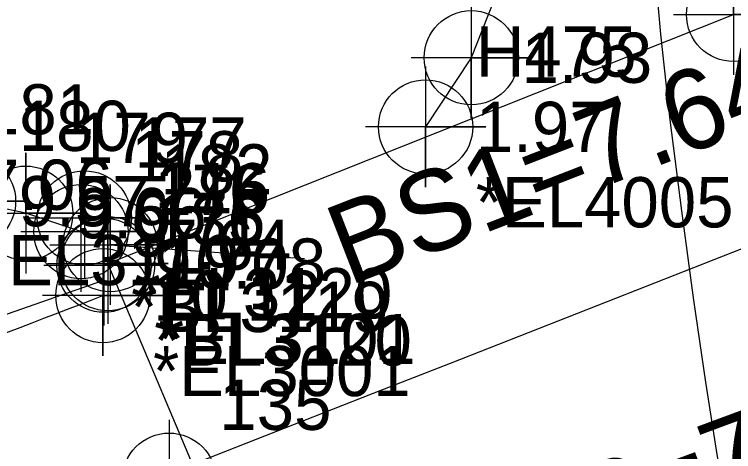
# Model space of a CAD drawing. Extents: x 2597630 to 2605918, y 617194 to 635093.
# Drawn here: x 2604047.61 to 2604083.41, y 618689.44 to 618711.2 of the extents above; entities that cross this region are included whole.
import ezdxf

# ---------------------------------------------------------------- set-up
doc = ezdxf.new("R2010")
doc.units = 0
for name, color, linetype in [('COGO Default Chain', 7, 'Continuous'), ('COGO Default Curve', 7, 'Continuous'), ('Exist DTM Breakline', 7, 'Continuous'), ('Exist DTM Breakline Cogo Comment', 7, 'Continuous'), ('Exist DTM Breakline Cogo Elevation', 7, 'Continuous'), ('Exist DTM Breakline Cogo Number', 7, 'Continuous'), ('Exist DTM Breakline Cogo Point CELL', 7, 'Continuous'), ('Exist DTM Crownline Cogo Number', 7, 'Continuous'), ('Exist DTM Crownline Cogo Point CELL', 7, 'Continuous'), ('Exist Guardrail', 7, 'Continuous'), ('Exist Horizontal Alignment', 7, 'Continuous'), ('Exist Hydro Stream or Body of Water', 7, 'Continuous'), ('Exist Right of Way Line', 7, 'Continuous'), ('Exist Roads EOP', 7, 'Continuous'), ('Exist Roads EOP Cogo Comment', 7, 'Continuous'), ('Exist Roads EOP Cogo Elevation', 7, 'Continuous'), ('Exist Roads EOP Cogo Number', 7, 'Continuous'), ('Exist Roads EOP Cogo Point CELL', 7, 'Continuous'), ('Exist Structure Major Bridge Seat Cogo Elevation', 7, 'Continuous'), ('Exist Structure Major Bridge Seat Cogo Number', 7, 'Continuous'), ('Exist Structure Major Bridge Seat Cogo Point CELL', 7, 'Continuous'), ('Exist Structure Major Bridge Seat Leader', 7, 'Continuous'), ('Exist Structure Major Bridge Seat Top Elevation', 7, 'Continuous'), ('Exist Structure Major Bridge WW', 7, 'Continuous'), ('Exist Structure Major Bridge WW Cogo Comment', 7, 'Continuous'), ('Exist Structure Major Bridge WW Cogo Elevation', 7, 'Continuous'), ('Exist Structure Major Bridge WW Cogo Number', 7, 'Continuous'), ('Exist Structure Major Bridge WW Cogo Point CELL', 7, 'Continuous'), ('Exist Structure Major Deck Tunnel Box Culvert', 7, 'Continuous'), ('Exist Structure Major Deck Tunnel Box Culvert Cogo Comment', 7, 'Continuous'), ('Exist Structure Major Deck Tunnel Box Culvert Cogo Elevation', 7, 'Continuous'), ('Exist Structure Major Deck Tunnel Box Culvert Cogo Number', 7, 'Continuous'), ('Exist Structure Major Deck Tunnel Box Culvert Cogo Point CELL', 7, 'Continuous'), ('Exist Structure Minor Head and End Wall Cogo Comment', 7, 'Continuous'), ('Exist Structure Minor Head and End Wall Cogo Elevation', 7, 'Continuous'), ('Exist Structure Minor Head and End Wall Cogo Number', 7, 'Continuous'), ('Exist Structure Minor Head and End Wall Cogo Point CELL', 7, 'Continuous')]:
    doc.layers.add(name, color=color, linetype=linetype)

# ---------------------------------------------------------------- blocks, each defined once
blk = doc.blocks.new('EXIST DTM BREAKLINE COGO POINT')
at = {"layer": 'Exist DTM Breakline Cogo Point CELL'}
blk.add_lwpolyline([(0, 0.06), (0, -0.06), (0, 0), (0.06, 0), (-0.06, 0)], dxfattribs=at)
blk.add_circle((0, 0), 0.04688, dxfattribs=at)
blk = doc.blocks.new('EXIST STRUCTURE MAJOR BRIDGE SEAT COGO POINT')
at = {"layer": 'Exist Structure Major Bridge Seat Cogo Point CELL'}
blk.add_lwpolyline([(-0.06, 0), (0.06, 0), (0, 0), (0, 0.06), (0, -0.06)], dxfattribs=at)
blk.add_circle((0, 0), 0.04688, dxfattribs=at)
blk = doc.blocks.new('EXIST DTM CROWNLINE COGO POINT')
at = {"layer": 'Exist DTM Crownline Cogo Point CELL'}
blk.add_lwpolyline([(0, 0.06), (0, -0.06), (0, 0), (0.06, 0), (-0.06, 0)], dxfattribs=at)
blk.add_circle((0, 0), 0.04688, dxfattribs=at)
blk = doc.blocks.new('EXIST ROADS EOP COGO POINT')
at = {"layer": 'Exist Roads EOP Cogo Point CELL'}
blk.add_lwpolyline([(0, 0.06), (0, -0.06), (0, 0), (0.06, 0), (-0.06, 0)], dxfattribs=at)
blk.add_circle((0, 0), 0.04688, dxfattribs=at)
blk = doc.blocks.new('EXIST STRUCTURE MINOR HEAD AND END WALL COGO POINT')
at = {"layer": 'Exist Structure Minor Head and End Wall Cogo Point CELL'}
blk.add_lwpolyline([(-0.06, 0), (0.06, 0), (0, 0), (0, 0.06), (0, -0.06)], dxfattribs=at)
blk.add_circle((0, 0), 0.04688, dxfattribs=at)
blk = doc.blocks.new('EXIST STRUCTURE MAJOR BRIDGE WW COGO POINT')
at = {"layer": 'Exist Structure Major Bridge WW Cogo Point CELL'}
blk.add_lwpolyline([(-0.06, 0), (0.06, 0), (0, 0), (0, 0.06), (0, -0.06)], dxfattribs=at)
blk.add_circle((0, 0), 0.04688, dxfattribs=at)
blk = doc.blocks.new('EXIST STRUCTURE MAJOR DECK TUNNEL BOX CULVERT COGO POINT')
at = {"layer": 'Exist Structure Major Deck Tunnel Box Culvert Cogo Point CELL'}
blk.add_lwpolyline([(-0.06, 0), (0.06, 0), (0, 0), (0, 0.06), (0, -0.06)], dxfattribs=at)
blk.add_circle((0, 0), 0.04688, dxfattribs=at)

msp = doc.modelspace()

# ---------------------------------------------------------------- linework, layer by layer
at = {"layer": 'COGO Default Chain'}
msp.add_arc((2597632.588, 635089.507), 17613.895, 290.3221155, 292.0583016, dxfattribs=at)
msp.add_arc((2597632.588, 635089.507), 17613.895, 290.3221155, 292.0583016, dxfattribs=at)
msp.add_arc((2597632.588, 635089.507), 17613.895, 290.3221155, 292.0583016, dxfattribs=at)
msp.add_arc((2597632.588, 635089.507), 17613.895, 290.3221155, 292.0583016, dxfattribs=at)
msp.add_arc((2597632.588, 635089.507), 17613.895, 290.3221155, 292.0583016, dxfattribs=at)
msp.add_arc((2597632.588, 635089.507), 17613.895, 290.3221155, 292.0583016, dxfattribs=at)
at = {"layer": 'COGO Default Curve'}
msp.add_arc((2597632.588, 635089.507), 17613.895, 290.3221155, 292.0583016, dxfattribs=at)
msp.add_arc((2597632.588, 635089.507), 17613.895, 290.3221155, 292.0583016, dxfattribs=at)
at = {"layer": 'Exist DTM Breakline'}
msp.add_lwpolyline([(2604073.23, 618725.574), (2604072.597, 618714.752), (2604070.352, 618709.039), (2604068.079, 618705.596)], dxfattribs=at)
at = {"layer": 'Exist Guardrail'}
msp.add_lwpolyline([(2604027.029, 618690.238), (2604028.032, 618689.57), (2604052.016, 618697.945)], dxfattribs=at)
at = {"layer": 'Exist Horizontal Alignment'}
msp.add_arc((2597632.588, 635089.507), 17613.895, 290.3221155, 292.0583016, dxfattribs=at)
at = {"layer": 'Exist Hydro Stream or Body of Water'}
msp.add_lwpolyline([(2604079.436, 618713.93), (2604079.767, 618710.215), (2604080.243, 618705.943), (2604080.811, 618701.424), (2604081.419, 618696.971), (2604082.012, 618692.895), (2604082.539, 618689.506), (2604082.793, 618687.973), (2604083.043, 618686.561), (2604083.41, 618684.573), (2604083.483, 618684.153)], dxfattribs=at)
at = {"layer": 'Exist Right of Way Line'}
msp.add_arc((2597632.588, 635089.507), 17584.22, 290.3221155, 291.5057379, dxfattribs=at)
at = {"layer": 'Exist Roads EOP'}
msp.add_spline([(2603230.17, 618389.98), (2603282.929, 618409.597), (2603332.773, 618427.868), (2603388.167, 618448.413), (2603437.203, 618466.721), (2603490.778, 618486.527), (2603539.039, 618504.558), (2603597.451, 618526.156), (2603651.053, 618545.972), (2603705.208, 618566.084), (2603762.02, 618587.183), (2603820.334, 618609.162), (2603876.341, 618629.99), (2603934.909, 618652.28), (2603996.409, 618675.568), (2604033.216, 618689.957), (2604052.01, 618697.199)], degree=3, dxfattribs=at)
at = {"layer": 'Exist Structure Major Bridge Seat Leader'}
msp.add_lwpolyline([(2604052.378, 618699.736), (2604062.046, 618699.043), (2604062.046, 618699.043)], dxfattribs=at)
at = {"layer": 'Exist Structure Major Bridge WW'}
msp.add_lwpolyline([(2604050.92, 618700.387), (2604048.172, 618701.305), (2604045.325, 618701.901), (2604043.496, 618702.72)], dxfattribs=at)
at = {"layer": 'Exist Structure Major Deck Tunnel Box Culvert'}
for p, q in [((2604052.256, 618698.794), (2604083.412, 618711.197)), ((2604052.256, 618698.794), (2604083.412, 618711.197)), ((2604061.588, 618676.727), (2604052.256, 618698.794)), ((2604061.588, 618676.727), (2604052.256, 618698.794))]:
    msp.add_line(p, q, dxfattribs=at)

# ---------------------------------------------------------------- block references
at = {"layer": 'Exist DTM Breakline Cogo Point CELL', "xscale": 50, "yscale": 50}
for p in [(2604070.352, 618709.039), (2604068.079, 618705.596)]:
    msp.add_blockref('EXIST DTM BREAKLINE COGO POINT', p, dxfattribs=at)
at = {"layer": 'Exist DTM Crownline Cogo Point CELL', "xscale": 50, "yscale": 50}
msp.add_blockref('EXIST DTM CROWNLINE COGO POINT', (2604055.311, 618688.017), dxfattribs=at)
msp.add_blockref('EXIST DTM CROWNLINE COGO POINT', (2604055.311, 618688.017), dxfattribs=at)
at = {"layer": 'Exist Roads EOP Cogo Point CELL', "xscale": 50, "yscale": 50}
msp.add_blockref('EXIST ROADS EOP COGO POINT', (2604052.01, 618697.199), dxfattribs=at)
msp.add_blockref('EXIST ROADS EOP COGO POINT', (2604052.01, 618697.199), dxfattribs=at)
at = {"layer": 'Exist Structure Major Bridge Seat Cogo Point CELL', "xscale": 50, "yscale": 50}
msp.add_blockref('EXIST STRUCTURE MAJOR BRIDGE SEAT COGO POINT', (2604052.378, 618699.736), dxfattribs=at)
msp.add_blockref('EXIST STRUCTURE MAJOR BRIDGE SEAT COGO POINT', (2604052.378, 618699.736), dxfattribs=at)
msp.add_blockref('EXIST STRUCTURE MAJOR BRIDGE SEAT COGO POINT', (2604052.378, 618699.736), dxfattribs=at)
msp.add_blockref('EXIST STRUCTURE MAJOR BRIDGE SEAT COGO POINT', (2604052.378, 618699.736), dxfattribs=at)
at = {"layer": 'Exist Structure Major Bridge WW Cogo Point CELL', "xscale": 50, "yscale": 50}
for p in [(2604045.325, 618701.901), (2604045.325, 618701.901), (2604045.325, 618701.901), (2604048.172, 618701.305), (2604048.172, 618701.305), (2604048.172, 618701.305), (2604050.92, 618700.387), (2604050.92, 618700.387), (2604050.92, 618700.387)]:
    msp.add_blockref('EXIST STRUCTURE MAJOR BRIDGE WW COGO POINT', p, dxfattribs=at)
at = {"layer": 'Exist Structure Major Deck Tunnel Box Culvert Cogo Point CELL', "xscale": 50, "yscale": 50}
for p in [(2604083.412, 618711.197), (2604083.412, 618711.197), (2604052.256, 618698.794), (2604052.256, 618698.794)]:
    msp.add_blockref('EXIST STRUCTURE MAJOR DECK TUNNEL BOX CULVERT COGO POINT', p, dxfattribs=at)
at = {"layer": 'Exist Structure Minor Head and End Wall Cogo Point CELL', "xscale": 50, "yscale": 50}
for p in [(2604051.09, 618701.069), (2604051.09, 618701.069), (2604052.067, 618698.714), (2604052.067, 618698.714)]:
    msp.add_blockref('EXIST STRUCTURE MINOR HEAD AND END WALL COGO POINT', p, dxfattribs=at)

# ---------------------------------------------------------------- texts
at = {"layer": 'Exist DTM Breakline Cogo Comment'}
msp.add_text('*EL4005', height=2.5, dxfattribs=at).set_placement((2604070.579, 618700.596))
at = {"layer": 'Exist DTM Breakline Cogo Elevation'}
for s, p in [('1.93', (2604072.852, 618707.789)), ('1.97', (2604070.579, 618704.346))]:
    msp.add_text(s, height=2.5, dxfattribs=at).set_placement(p)
at = {"layer": 'Exist DTM Breakline Cogo Number'}
msp.add_text('H475', height=2.5, dxfattribs=at).set_placement((2604070.579, 618708.096))
at = {"layer": 'Exist DTM Crownline Cogo Number'}
msp.add_text('135', height=2.5, dxfattribs=at).set_placement((2604057.811, 618690.517))
msp.add_text('135', height=2.5, dxfattribs=at).set_placement((2604057.811, 618690.517))
at = {"layer": 'Exist Roads EOP Cogo Comment'}
msp.add_text('*EL3001', height=2.5, dxfattribs=at).set_placement((2604054.51, 618692.199))
at = {"layer": 'Exist Roads EOP Cogo Elevation'}
msp.add_text('10.12', height=2.5, dxfattribs=at).set_placement((2604054.51, 618695.949))
at = {"layer": 'Exist Roads EOP Cogo Number'}
msp.add_text('136', height=2.5, dxfattribs=at).set_placement((2604054.51, 618699.699))
at = {"layer": 'Exist Structure Major Bridge Seat Cogo Elevation'}
msp.add_text('7.64', height=2.5, dxfattribs=at).set_placement((2604054.878, 618698.486))
msp.add_text('7.64', height=2.5, dxfattribs=at).set_placement((2604054.878, 618698.486))
msp.add_text('7.64', height=2.5, dxfattribs=at).set_placement((2604054.878, 618698.486))
at = {"layer": 'Exist Structure Major Bridge Seat Cogo Number'}
msp.add_text('182', height=2.5, dxfattribs=at).set_placement((2604054.878, 618702.236))
msp.add_text('182', height=2.5, dxfattribs=at).set_placement((2604054.878, 618702.236))
msp.add_text('182', height=2.5, dxfattribs=at).set_placement((2604054.878, 618702.236))
at = {"layer": 'Exist Structure Major Bridge Seat Top Elevation'}
for s, rotation, p in [("BS1=7.64'", 21.2098, (2604064.244, 618697.666)), ("BS2=7.61'", 20.3433, (2604070.321, 618682.231))]:
    msp.add_text(s, height=4, rotation=rotation, dxfattribs=at).set_placement(p)
at = {"layer": 'Exist Structure Major Bridge WW Cogo Comment'}
for s, p in [('*EL3119', (2604045.996, 618697.72)), ('*BL3119', (2604053.42, 618695.387))]:
    msp.add_text(s, height=2.5, dxfattribs=at).set_placement(p)
at = {"layer": 'Exist Structure Major Bridge WW Cogo Elevation'}
for s, p in [('7.06', (2604045.996, 618701.47)), ('9.57', (2604047.825, 618700.651)), ('9.66', (2604050.672, 618700.055)), ('9.71', (2604053.42, 618699.137))]:
    msp.add_text(s, height=2.5, dxfattribs=at).set_placement(p)
at = {"layer": 'Exist Structure Major Bridge WW Cogo Number'}
for s, p in [('181', (2604045.996, 618705.22)), ('180', (2604047.825, 618704.401)), ('179', (2604050.672, 618703.805)), ('178', (2604053.42, 618702.887))]:
    msp.add_text(s, height=2.5, dxfattribs=at).set_placement(p)
at = {"layer": 'Exist Structure Major Deck Tunnel Box Culvert Cogo Comment'}
msp.add_text('*EL3101', height=2.5, dxfattribs=at).set_placement((2604054.756, 618693.794))
at = {"layer": 'Exist Structure Major Deck Tunnel Box Culvert Cogo Elevation'}
msp.add_text('10.08', height=2.5, dxfattribs=at).set_placement((2604054.756, 618697.544))
at = {"layer": 'Exist Structure Major Deck Tunnel Box Culvert Cogo Number'}
msp.add_text('216', height=2.5, dxfattribs=at).set_placement((2604054.756, 618701.294))
at = {"layer": 'Exist Structure Minor Head and End Wall Cogo Comment'}
for s, p in [('*EL3120', (2604053.59, 618696.069)), ('*BL3120', (2604054.567, 618693.714))]:
    msp.add_text(s, height=2.5, dxfattribs=at).set_placement(p)
at = {"layer": 'Exist Structure Minor Head and End Wall Cogo Elevation'}
for s, p in [('9.75', (2604053.59, 618699.819)), ('9.77', (2604054.567, 618697.464))]:
    msp.add_text(s, height=2.5, dxfattribs=at).set_placement(p)
at = {"layer": 'Exist Structure Minor Head and End Wall Cogo Number'}
for s, p in [('177', (2604053.59, 618703.569)), ('176', (2604054.567, 618701.214))]:
    msp.add_text(s, height=2.5, dxfattribs=at).set_placement(p)

doc.saveas('drawing.dxf')
